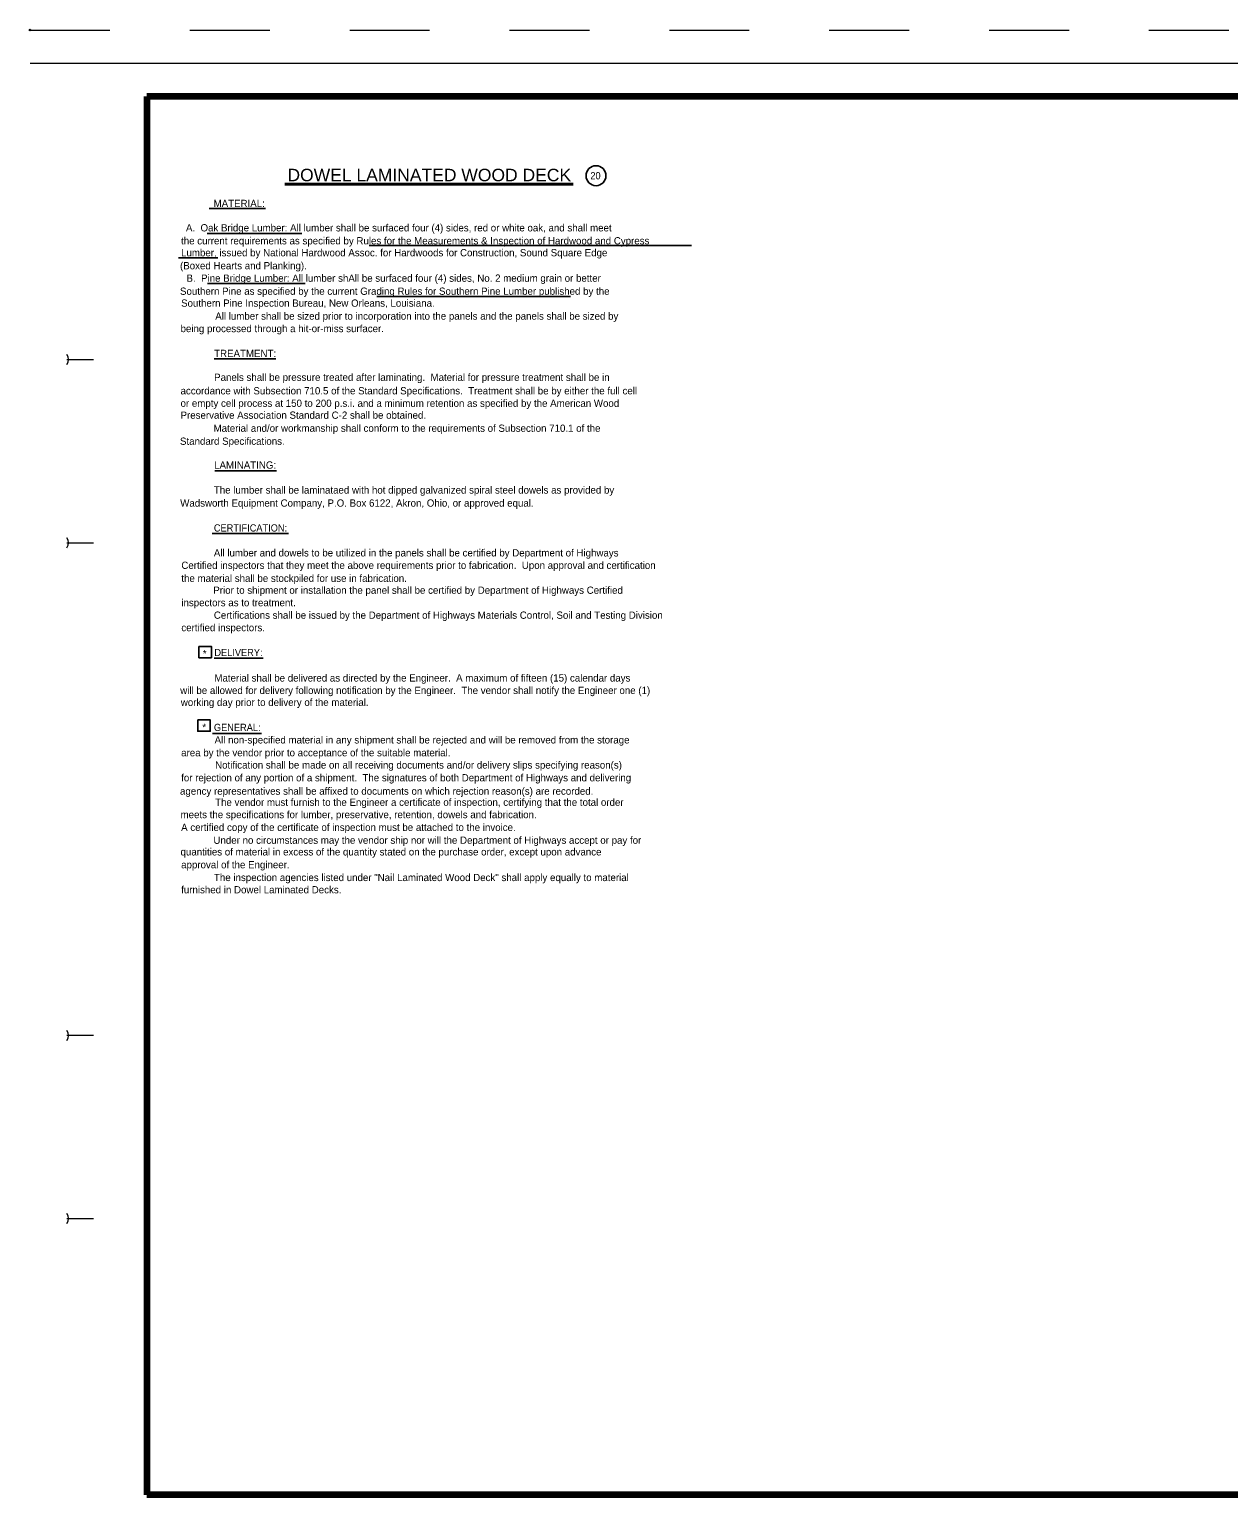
# Model space of a CAD drawing. Extents: x -2.94 to 3.45, y 0.57 to 4.
# Drawn here: x -2.936 to -1.435, y 2.17 to 4.004 of the extents above; entities that cross this region are included whole.
import ezdxf
from ezdxf.enums import TextEntityAlignment as Align

# ---------------------------------------------------------------- set-up
doc = ezdxf.new("R2010")
doc.units = 0
doc.header["$LTSCALE"] = 0.0036
doc.header["$PDMODE"] = 32
doc.header["$PDSIZE"] = 0.0018
doc.linetypes.add('LONG_DASHED', pattern=[7.5, 6, -1.5])
doc.layers.add('1', color=7, linetype='Continuous', lineweight=13)
doc.layers.add('3', color=7, linetype='Continuous', lineweight=25)

msp = doc.modelspace()

# ---------------------------------------------------------------- linework, layer by layer
at = {"layer": '1', "linetype": 'LONG_DASHED'}
msp.add_line((-2.935167, 4.002917), (0.065333, 4.002917), dxfattribs=at)
at = {"layer": '1'}
for p, q in [((-2.935167, 3.96125), (0.065333, 3.96125)), ((-2.889083, 3.590417), (-2.85575, 3.590417)), ((-2.889083, 3.36125), (-2.85575, 3.36125)), ((-2.889083, 2.744667), (-2.85575, 2.744667)), ((-2.889083, 2.515417), (-2.85575, 2.515417))]:
    msp.add_line(p, q, dxfattribs=at)
at = {"layer": '1', "lineweight": 158}
for p, q in [((0.023417, 3.919667), (-2.789083, 3.919667)), ((-2.789083, 3.919667), (-2.789083, 2.169667)), ((0.023417, 2.169667), (-2.789083, 2.169667))]:
    msp.add_line(p, q, dxfattribs=at)
at = {"layer": '1'}
for centre, start, end in [((-2.897417, 3.590417), 323.13009, 36.86989), ((-2.897417, 3.36125), 323.13009, 36.50143), ((-2.897417, 2.744583), 322.67175, 36.41154), ((-2.897417, 2.515417), 323.13009, 36.86989)]:
    msp.add_arc(centre, 0.010417, start, end, dxfattribs=at)
msp.add_point((-2.935167, 4.002917), dxfattribs=at)
at = {"layer": '3', "lineweight": 40}
msp.add_line((-2.616417, 3.809917), (-2.255417, 3.809917), dxfattribs=at)
at = {"layer": '3'}
for p, q in [((-2.710917, 3.779333), (-2.640417, 3.779333)), ((-2.713583, 3.748167), (-2.595, 3.748167)), ((-2.510917, 3.73325), (-2.107583, 3.73325)), ((-2.749583, 3.717667), (-2.700083, 3.717667)), ((-2.712917, 3.68575), (-2.590917, 3.68575)), ((-2.501417, 3.6695), (-2.25875, 3.6695)), ((-2.704833, 3.5915), (-2.6275, 3.5915)), ((-2.704083, 3.45125), (-2.62675, 3.45125)), ((-2.707417, 3.372583), (-2.611667, 3.372583)), ((-2.70475, 3.21675), (-2.6435, 3.21675)), ((-2.706833, 3.122583), (-2.645583, 3.122583))]:
    msp.add_line(p, q, dxfattribs=at)
for points in [[(-2.723833, 3.2315), (-2.723833, 3.21725), (-2.70825, 3.21725), (-2.70825, 3.2315)], [(-2.72525, 3.139417), (-2.72525, 3.125167), (-2.709667, 3.125167), (-2.709667, 3.139417)]]:
    msp.add_lwpolyline(points, close=True, dxfattribs=at)
msp.add_circle((-2.227, 3.820583), 0.0125, dxfattribs=at)

# ---------------------------------------------------------------- texts
for s, height, width, p in [('DOWEL LAMINATED WOOD DECK', 0.01558, 1.05, (-2.435625, 3.813667)), ('20', 0.009083, 0.95, (-2.227625, 3.816083))]:
    msp.add_text(s, height=height, dxfattribs=dict(at, width=width)).set_placement(p, align=Align.CENTER)
for s, p in [('MATERIAL:', (-2.7055, 3.781333)), ('  A.  Oak Bridge Lumber: All lumber shall be surfaced four (4) sides, red or white oak, and shall meet', (-2.746833, 3.750833)), ('the current requirements as specified by Rules for the Measurements & Inspection of Hardwood and Cypress', (-2.746167, 3.734583)), ('Lumber, issued by National Hardwood Assoc. for Hardwoods for Construction, Sound Square Edge', (-2.746167, 3.719667)), ('(Boxed Hearts and Planking).', (-2.7475, 3.703417)), ('  B.  Pine Bridge Lumber: All lumber shAll be surfaced four (4) sides, No. 2 medium grain or better', (-2.746167, 3.687833)), ('Southern Pine as specified by the current Grading Rules for Southern Pine Lumber published by the', (-2.7475, 3.6715)), ('Southern Pine Inspection Bureau, New Orleans, Louisiana.', (-2.746167, 3.656583)), ('being processed through a hit-or-miss surfacer.', (-2.746833, 3.62475)), ('All lumber shall be sized prior to incorporation into the panels and the panels shall be sized by', (-2.703417, 3.640333)), ('TREATMENT:', (-2.704833, 3.593583)), ('Panels shall be pressure treated after laminating.  Material for pressure treatment shall be in', (-2.704833, 3.56375)), ('or empty cell process at 150 to 200 p.s.i. and a minimum retention as specified by the American Wood', (-2.746833, 3.53125)), ('accordance with Subsection 710.5 of the Standard Specifications.  Treatment shall be by either the full cell', (-2.746833, 3.546833)), ('Preservative Association Standard C-2 shall be obtained.', (-2.746833, 3.516333)), ('Material and/or workmanship shall conform to the requirements of Subsection 710.1 of the', (-2.7055, 3.5)), ('Standard Specifications.', (-2.7475, 3.48375)), ('LAMINATING:', (-2.704833, 3.453917)), ('The lumber shall be laminataed with hot dipped galvanized spiral steel dowels as provided by ', (-2.705167, 3.422667)), ('Wadsworth Equipment Company, P.O. Box 6122, Akron, Ohio, or approved equal.', (-2.74725, 3.406333)), ('All lumber and dowels to be utilized in the panels shall be certified by Department of Highways', (-2.705167, 3.344)), ('the material shall be stockpiled for use in fabrication.', (-2.745833, 3.312167)), ('Certified inspectors that they meet the above requirements prior to fabrication.  Upon approval and certification ', (-2.745833, 3.328417)), ('Prior to shipment or installation the panel shall be certified by Department of Highways Certified', (-2.705833, 3.29725)), ('inspectors as to treatment.', (-2.745833, 3.281667)), ('Certifications shall be issued by the Department of Highways Materials Control, Soil and Testing Division', (-2.705167, 3.266)), ('certified inspectors.', (-2.745833, 3.250417)), ('*', (-2.718917, 3.217917)), ('Material shall be delivered as directed by the Engineer.  A maximum of fifteen (15) calendar days', (-2.7045, 3.187417)), ('will be allowed for delivery following notification by the Engineer.  The vendor shall notify the Engineer one (1)', (-2.74725, 3.171833)), ('working day prior to delivery of the material.', (-2.7465, 3.156917)), ('*', (-2.719583, 3.125833)), ('All non-specified material in any shipment shall be rejected and will be removed from the storage', (-2.70425, 3.109917)), ('area by the vendor prior to acceptance of the suitable material.', (-2.746083, 3.093833)), ('Notification shall be made on all receiving documents and/or delivery slips specifying reason(s)', (-2.703583, 3.0785)), ('for rejection of any portion of a shipment.  The signatures of both Department of Highways and delivering', (-2.746083, 3.0625)), ('agency representatives shall be affixed to documents on which rejection reason(s) are recorded.', (-2.7475, 3.04575)), ('The vendor must furnish to the Engineer a certificate of inspection, certifying that the total order', (-2.703583, 3.031833)), ('A certified copy of the certificate of inspection must be attached to the invoice.', (-2.746083, 3.000417)), ('meets the specifications for lumber, preservative, retention, dowels and fabrication.', (-2.746833, 3.016417)), ('Under no circumstances may the vendor ship nor will the Department of Highways accept or pay for', (-2.705667, 2.984333)), ('quantities of material in excess of the quantity stated on the purchase order, except upon advance', (-2.746833, 2.96975)), ('approval of the Engineer.', (-2.746083, 2.953667)), ('The inspection agencies listed under "Nail Laminated Wood Deck" shall apply equally to material ', (-2.705, 2.937667)), ('furnished in Dowel Laminated Decks.', (-2.746083, 2.922333))]:
    msp.add_text(s, height=0.009083, dxfattribs=at).set_placement(p)
at = {"layer": '3', "width": 0.95}
for s, p in [('CERTIFICATION:', (-2.705167, 3.375167)), ('DELIVERY:', (-2.7045, 3.21925)), ('GENERAL:', (-2.705083, 3.1255))]:
    msp.add_text(s, height=0.009083, dxfattribs=at).set_placement(p)

doc.saveas('drawing.dxf')
